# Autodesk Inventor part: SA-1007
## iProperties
Created: 2004-11
Part Number: SA-1007
Cost Center: 0 lbmass
Document SubType Name: Modeling
Designer: busseym
Manufacturer: Standard
Standards Organization: Custom
Stock Number: P-1267
Density: 1 g/cm^3
CAGE: 1LJX3
Dept. ID: Product Design
Description #2: ---
Finish #1: ---
Finish #2: ---
Material ID: ---
Project Number: ---
Author: busseym
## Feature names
1. Extrusion1
2. Extrusion2
3. Extrusion4
4. Circular Pattern1
5. Mirror1
6. Extrusion3
7. Mirror2
